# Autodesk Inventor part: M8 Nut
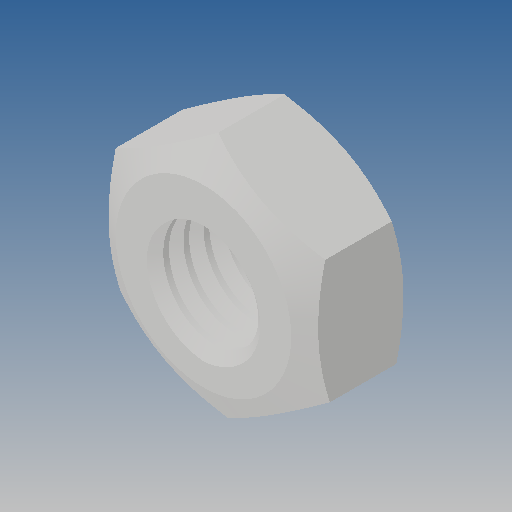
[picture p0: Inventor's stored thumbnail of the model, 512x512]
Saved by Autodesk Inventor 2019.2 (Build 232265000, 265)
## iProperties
Created: 2013-03
Part Number: M8 Nut
Material: Ogólny
Document SubType Name: Modeling
Designer: CADENGINEERING4
Density: 1 g/cm^3
Appearance: Domyślna
Author: CADENGINEERING4
Revision Number: ÈÎºÎ
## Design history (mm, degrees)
feature "ÇÐ³ý-É¨Ãè1"
node "Bryła1"
